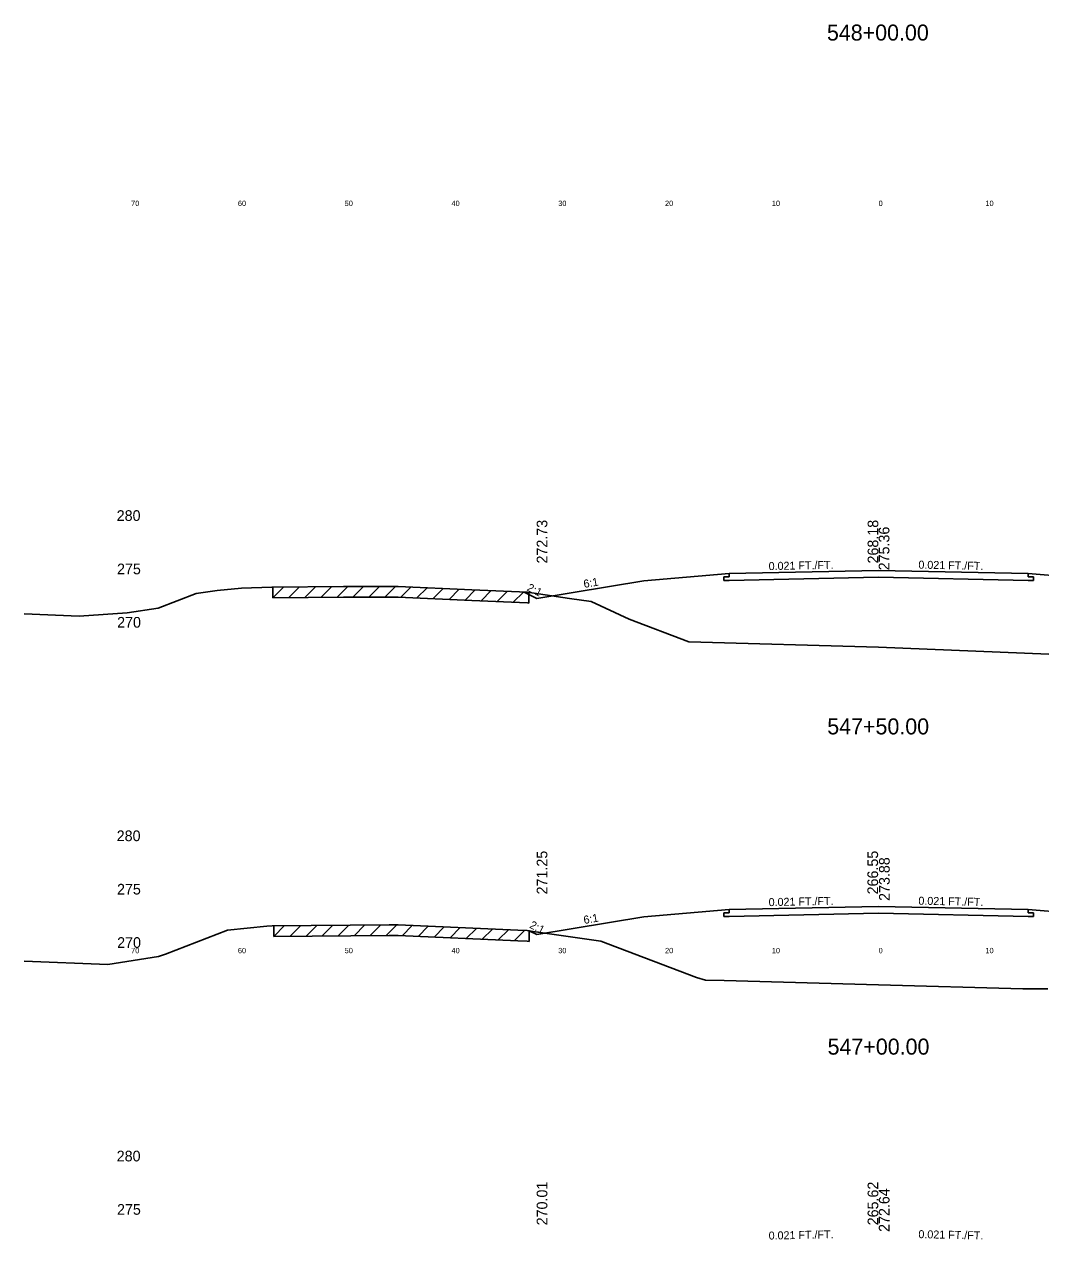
# Model space of a CAD drawing. Extents: x 1000 to 1162, y 999 to 8520.
# Drawn here: x 1000 to 1095.2, y 6882.7 to 6996.5 of the extents above; entities that cross this region are included whole.
import ezdxf

# ---------------------------------------------------------------- set-up
doc = ezdxf.new("R2010")
doc.units = 0
for name, color, linetype in [('Level 10', 7, 'Continuous'), ('Level 11', 7, 'Continuous'), ('Level 12', 7, 'Continuous'), ('Level 3', 7, 'Continuous'), ('Level 32', 7, 'Continuous'), ('Level 33', 7, 'Continuous'), ('Level 56', 7, 'Continuous'), ('Level 59', 7, 'Continuous'), ('Level 6', 7, 'Continuous'), ('Level 60', 7, 'Continuous'), ('Level 61', 7, 'Continuous'), ('Level 7', 7, 'Continuous')]:
    doc.layers.add(name, color=color, linetype=linetype)

msp = doc.modelspace()

# ---------------------------------------------------------------- linework, layer by layer
at = {"layer": 'Level 11'}
for p, q in [((1066, 6944.76), (1065.5, 6944.75)), ((1065.5, 6944.75), (1065.5, 6944.41)), ((1065.5, 6944.41), (1066, 6944.42)), ((1066, 6945.06), (1066, 6944.76)), ((1094, 6944.76), (1094, 6945.06)), ((1094.5, 6944.75), (1094, 6944.76)), ((1094, 6944.42), (1094.5, 6944.41)), ((1094.5, 6944.41), (1094.5, 6944.75)), ((1066, 6913.59), (1066, 6913.29)), ((1094, 6913.29), (1094, 6913.59)), ((1066, 6913.29), (1065.5, 6913.27)), ((1065.5, 6913.27), (1065.5, 6912.93)), ((1065.5, 6912.93), (1066, 6912.95)), ((1094.5, 6913.27), (1094, 6913.29)), ((1094, 6912.95), (1094.5, 6912.93)), ((1094.5, 6912.93), (1094.5, 6913.27))]:
    msp.add_line(p, q, dxfattribs=at)
at = {"layer": 'Level 12'}
for p, q in [((1080, 6944.72), (1066, 6944.42)), ((1094, 6944.42), (1080, 6944.72)), ((1080, 6913.24), (1066, 6912.95)), ((1094, 6912.95), (1080, 6913.24))]:
    msp.add_line(p, q, dxfattribs=at)
at = {"layer": 'Level 59'}
for p, q in [((1066, 6945.06), (1080, 6945.36)), ((1080, 6945.36), (1094, 6945.06)), ((1066, 6913.59), (1080, 6913.88)), ((1080, 6913.88), (1094, 6913.59))]:
    msp.add_line(p, q, dxfattribs=at)
at = {"layer": 'Level 6'}
for p, q in [((1058, 6944.4), (1066, 6945.06)), ((1094, 6945.06), (1102, 6944.4)), ((1058, 6912.92), (1066, 6913.59)), ((1094, 6913.59), (1102, 6912.92))]:
    msp.add_line(p, q, dxfattribs=at)
at = {"layer": 'Level 60'}
for p, q in [((1012.54, 6941.84), (1016.08, 6943.21)), ((1016.08, 6943.21), (1018.06, 6943.48)), ((1018.06, 6943.48), (1020.34, 6943.7)), ((1020.34, 6943.7), (1023.18, 6943.8)), ((1023.18, 6943.8), (1029.9, 6943.85)), ((1029.9, 6943.85), (1035.01, 6943.86)), ((1035.01, 6943.86), (1041.91, 6943.55)), ((1041.91, 6943.55), (1047.12, 6943.32)), ((1047.12, 6943.32), (1051.05, 6942.74)), ((1051.05, 6942.74), (1053.09, 6942.46)), ((1053.09, 6942.46), (1056.64, 6940.79)), ((1000, 6941.29), (1005.14, 6941.08)), ((1005.14, 6941.08), (1009.63, 6941.38)), ((1009.63, 6941.38), (1012.54, 6941.84)), ((1056.64, 6940.79), (1062.23, 6938.68)), ((1062.23, 6938.68), (1080, 6938.18)), ((1080, 6938.18), (1095.94, 6937.52)), ((1013.22, 6909.41), (1019.02, 6911.66)), ((1019.02, 6911.66), (1022.72, 6912.03)), ((1022.72, 6912.03), (1023.22, 6912.08)), ((1023.22, 6912.08), (1034.16, 6912.16)), ((1034.16, 6912.16), (1035.01, 6912.16)), ((1035.01, 6912.16), (1046.21, 6911.66)), ((1046.21, 6911.66), (1047.08, 6911.64)), ((1047.08, 6911.64), (1047.66, 6911.55)), ((1047.66, 6911.55), (1053.99, 6910.62)), ((1053.99, 6910.62), (1062.95, 6907.24)), ((1007.81, 6908.44), (1012.57, 6909.18)), ((1012.57, 6909.18), (1013.22, 6909.41)), ((1000, 6908.76), (1007.81, 6908.44)), ((1062.95, 6907.24), (1063.79, 6906.98)), ((1063.79, 6906.98), (1065.54, 6906.96)), ((1065.54, 6906.96), (1080, 6906.55)), ((1080, 6906.55), (1093.52, 6906.17)), ((1093.52, 6906.17), (1095.85, 6906.17))]:
    msp.add_line(p, q, dxfattribs=at)
at = {"layer": 'Level 61'}
for p, q in [((1024.28, 6943.8), (1023.27, 6942.8)), ((1023.27, 6943.8), (1023.27, 6942.8)), ((1025.78, 6943.82), (1024.77, 6942.81)), ((1027.28, 6943.83), (1026.27, 6942.82)), ((1028.78, 6943.84), (1027.77, 6942.83)), ((1030.28, 6943.85), (1029.27, 6942.84)), ((1031.77, 6943.85), (1030.77, 6942.85)), ((1033.27, 6943.86), (1032.27, 6942.85)), ((1034.77, 6943.86), (1033.77, 6942.86)), ((1036.23, 6943.81), (1035.27, 6942.85)), ((1037.73, 6943.74), (1036.77, 6942.78)), ((1039.23, 6943.67), (1038.27, 6942.71)), ((1040.73, 6943.6), (1039.77, 6942.65)), ((1042.23, 6943.54), (1041.27, 6942.58)), ((1043.73, 6943.47), (1042.77, 6942.51)), ((1045.23, 6943.4), (1044.27, 6942.45)), ((1046.73, 6943.34), (1045.77, 6942.38)), ((1047.26, 6942.3), (1047.26, 6943.3)), ((1023.27, 6942.8), (1029.9, 6942.85)), ((1029.9, 6942.85), (1035.01, 6942.86)), ((1035.01, 6942.86), (1041.91, 6942.55)), ((1041.91, 6942.55), (1047.12, 6942.32)), ((1047.12, 6942.32), (1047.26, 6942.3)), ((1024.38, 6912.09), (1023.38, 6911.08)), ((1023.38, 6912.08), (1023.38, 6911.08)), ((1025.88, 6912.1), (1024.88, 6911.09)), ((1027.38, 6912.11), (1026.38, 6911.1)), ((1028.88, 6912.12), (1027.88, 6911.12)), ((1030.38, 6912.13), (1029.38, 6911.13)), ((1031.88, 6912.15), (1030.88, 6911.14)), ((1033.38, 6912.16), (1032.38, 6911.15)), ((1034.87, 6912.16), (1033.88, 6911.16)), ((1036.33, 6912.1), (1035.38, 6911.14)), ((1037.83, 6912.03), (1036.88, 6911.08)), ((1039.33, 6911.96), (1038.38, 6911.01)), ((1040.83, 6911.9), (1039.88, 6910.94)), ((1042.33, 6911.83), (1041.38, 6910.87)), ((1043.83, 6911.76), (1042.88, 6910.81)), ((1045.33, 6911.7), (1044.38, 6910.74)), ((1046.85, 6911.64), (1045.88, 6910.67)), ((1047.27, 6910.61), (1047.27, 6911.61)), ((1023.38, 6911.08), (1034.16, 6911.16)), ((1034.16, 6911.16), (1035.01, 6911.16)), ((1035.01, 6911.16), (1046.21, 6910.66)), ((1046.21, 6910.66), (1047.08, 6910.64)), ((1047.08, 6910.64), (1047.27, 6910.61))]:
    msp.add_line(p, q, dxfattribs=at)
at = {"layer": 'Level 7'}
for p, q in [((1048, 6942.73), (1058, 6944.4)), ((1046.8, 6943.33), (1048, 6942.73)), ((1048, 6911.25), (1058, 6912.92)), ((1047.29, 6911.6), (1048, 6911.25))]:
    msp.add_line(p, q, dxfattribs=at)

# ---------------------------------------------------------------- texts
at = {"layer": 'Level 10'}
for s, p in [('268.18', (1079.97, 6946.01)), ('266.55', (1079.95, 6915.01)), ('265.62', (1079.97, 6884.01))]:
    msp.add_text(s, height=1, rotation=90, dxfattribs=at).set_placement(p)
at = {"layer": 'Level 11'}
for s, p in [(' 280', (1008.28, 6950)), (' 275', (1008.31, 6945)), (' 270', (1008.32, 6940)), (' 280', (1008.28, 6920)), (' 275', (1008.31, 6915)), (' 270', (1008.32, 6910)), (' 280', (1008.28, 6890)), (' 275', (1008.31, 6885))]:
    msp.add_text(s, height=1, dxfattribs=at).set_placement(p)
at = {"layer": 'Level 3'}
for s, p in [('548+00.00', (1075.16, 6995)), ('547+50.00', (1075.19, 6930)), ('547+00.00', (1075.22, 6900))]:
    msp.add_text(s, height=1.5, dxfattribs=at).set_placement(p)
at = {"layer": 'Level 32'}
for s, rotation, p in [('0.021 FT./FT.', 1.1916, (1069.71, 6945.39)), ('0.021 FT./FT.', 358.8084, (1083.72, 6945.53)), ('6:1', 9.4623, (1052.43, 6943.72)), ('2:1', 333.435, (1047, 6943.51)), ('0.021 FT./FT.', 1.1916, (1069.71, 6913.91)), ('0.021 FT./FT.', 358.8084, (1083.72, 6914.05)), ('2:1', 333.435, (1047.25, 6911.91)), ('6:1', 9.4623, (1052.43, 6912.24)), ('0.021 FT./FT.', 1.1916, (1069.71, 6882.67)), ('0.021 FT./FT.', 358.8084, (1083.72, 6882.81))]:
    msp.add_text(s, height=0.75, rotation=rotation, dxfattribs=at).set_placement(p)
at = {"layer": 'Level 33'}
for s, p in [('272.73', (1048.98, 6946.01)), ('271.25', (1048.98, 6915.01)), ('270.01', (1048.98, 6884.01))]:
    msp.add_text(s, height=1, rotation=90, dxfattribs=at).set_placement(p)
at = {"layer": 'Level 56'}
for s, p in [('70', (1010, 6979.5)), ('60', (1020, 6979.5)), ('50', (1030, 6979.5)), ('40', (1040, 6979.5)), ('30', (1050, 6979.5)), ('20', (1060, 6979.5)), ('10', (1070, 6979.5)), ('0', (1080, 6979.5)), ('10', (1090, 6979.5)), ('70', (1010, 6909.5)), ('60', (1020, 6909.5)), ('50', (1030, 6909.5)), ('40', (1040, 6909.5)), ('30', (1050, 6909.5)), ('20', (1060, 6909.5)), ('10', (1070, 6909.5)), ('0', (1080, 6909.5)), ('10', (1090, 6909.5))]:
    msp.add_text(s, height=0.5, dxfattribs=at).set_placement(p)
at = {"layer": 'Level 59'}
for s, p in [(' 275.36', (1081.01, 6945)), (' 273.88', (1081.04, 6914.03)), (' 272.64', (1081.02, 6883.02))]:
    msp.add_text(s, height=1, rotation=90, dxfattribs=at).set_placement(p)

doc.saveas('drawing.dxf')
